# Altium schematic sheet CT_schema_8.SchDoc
size 278 x 170 mm
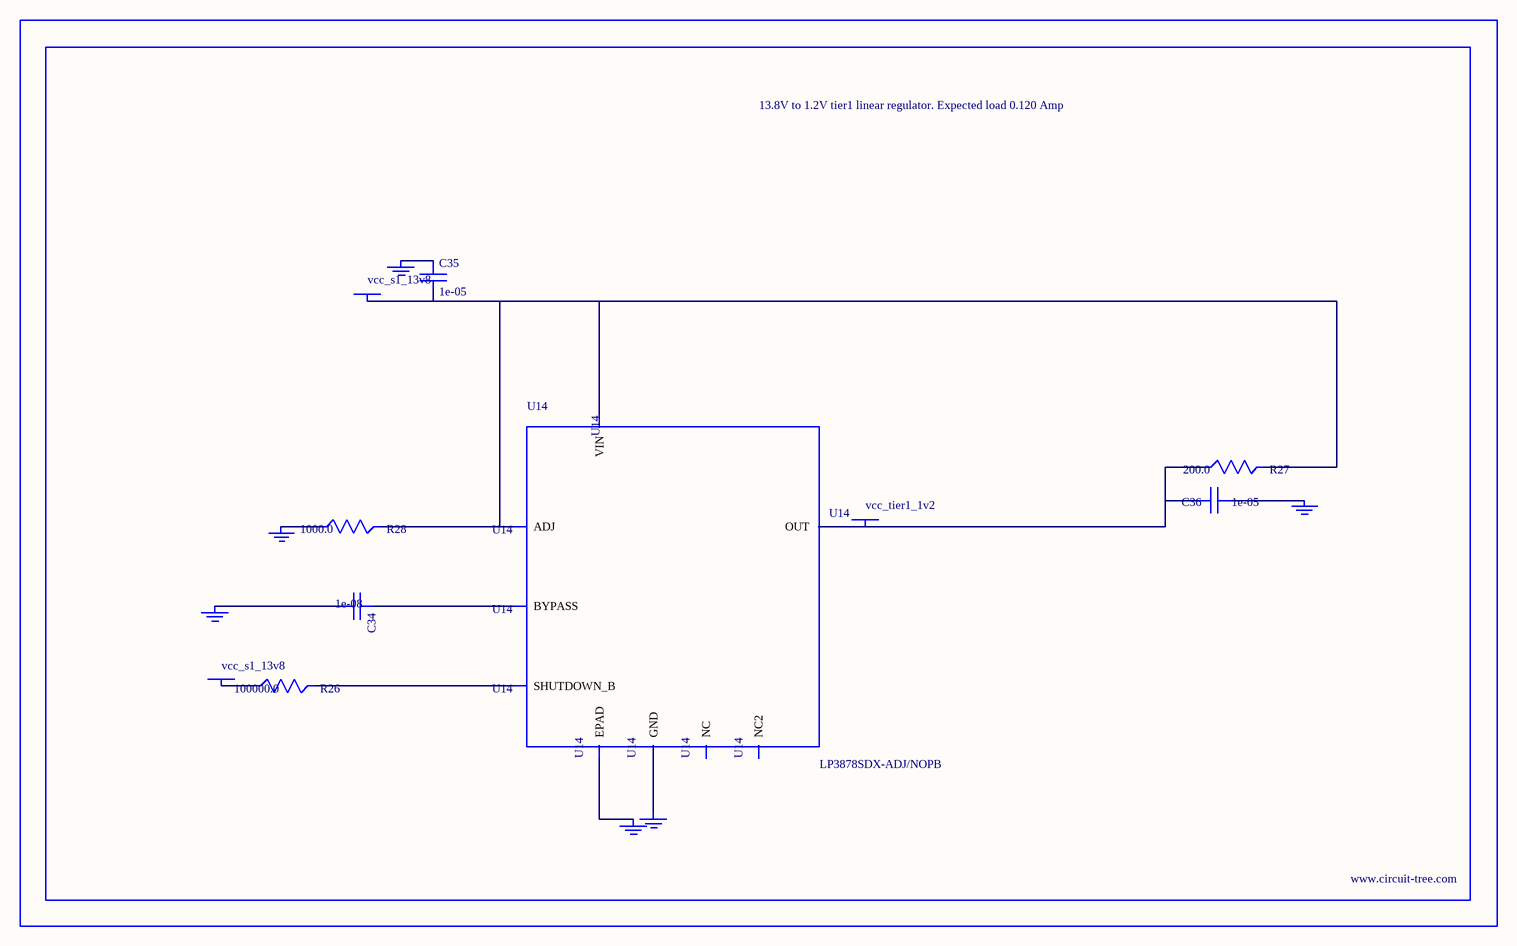
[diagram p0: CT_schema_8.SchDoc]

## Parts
BORDER7  (no value)
C34  1e-08  [C0402]
C35  1e-05  [C1210]
C36  1e-05  [C0805]
GND_INSTANCE_7_0  (no value)
GND_INSTANCE_7_1  (no value)
GND_INSTANCE_7_2  (no value)
GND_INSTANCE_7_3  (no value)
GND_INSTANCE_7_4  (no value)
GND_INSTANCE_7_5  (no value)
POWER_INSTANCE_7_0  vcc_s1_13v8
POWER_INSTANCE_7_1  vcc_s1_13v8
POWER_INSTANCE_7_2  vcc_tier1_1v2
R26  100000.0  [R0603]
R27  200.0  [R0603]
R28  1000.0  [R0603]
U14  LP3878SDX-ADJ/NOPB  [WSON-8]

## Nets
NetC34_1: C34.1 U14.1(BYPASS)
NetC34_2: C34.2 GND_INSTANCE_7_0.0(GND)
NetC35_1: C35.1 GND_INSTANCE_7_1.0(GND)
NetC35_2: C35.2 POWER_INSTANCE_7_0.0(PWR) R27.2 R28.2 U14.4(VIN) U14.6(ADJ)
NetC36_1: C36.1 GND_INSTANCE_7_2.0(GND)
NetC36_2: C36.2 POWER_INSTANCE_7_2.0(PWR) R27.1 U14.5(OUT)
NetGND_INSTANCE_7_3_0: GND_INSTANCE_7_3.0(GND) R28.1
NetGND_INSTANCE_7_4_0: GND_INSTANCE_7_4.0(GND) U14.PAD(EPAD)
NetGND_INSTANCE_7_5_0: GND_INSTANCE_7_5.0(GND) U14.3(GND)
NetPOWER_INSTANCE_7_1_0: POWER_INSTANCE_7_1.0(PWR) R26.1
NetR26_2: R26.2 U14.8(SHUTDOWN_B)

Not connected (* = marked no-connect by the designer): U14 2(NC) 7(NC2)

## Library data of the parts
BORDER7 = BORDER_PAGE7
C34 = C0402C103K3RAC
C35 = C1210C106K5PACTU
C36 = GRM219R60J106ME19D
GND_INSTANCE_7_0-GND_INSTANCE_7_5 = GND
POWER_INSTANCE_7_0-POWER_INSTANCE_7_2 = PWR
R26 = RC0603JR-07100KL
R27 = RC0603JR-07200RL
R28 = RC0603JR-071KL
